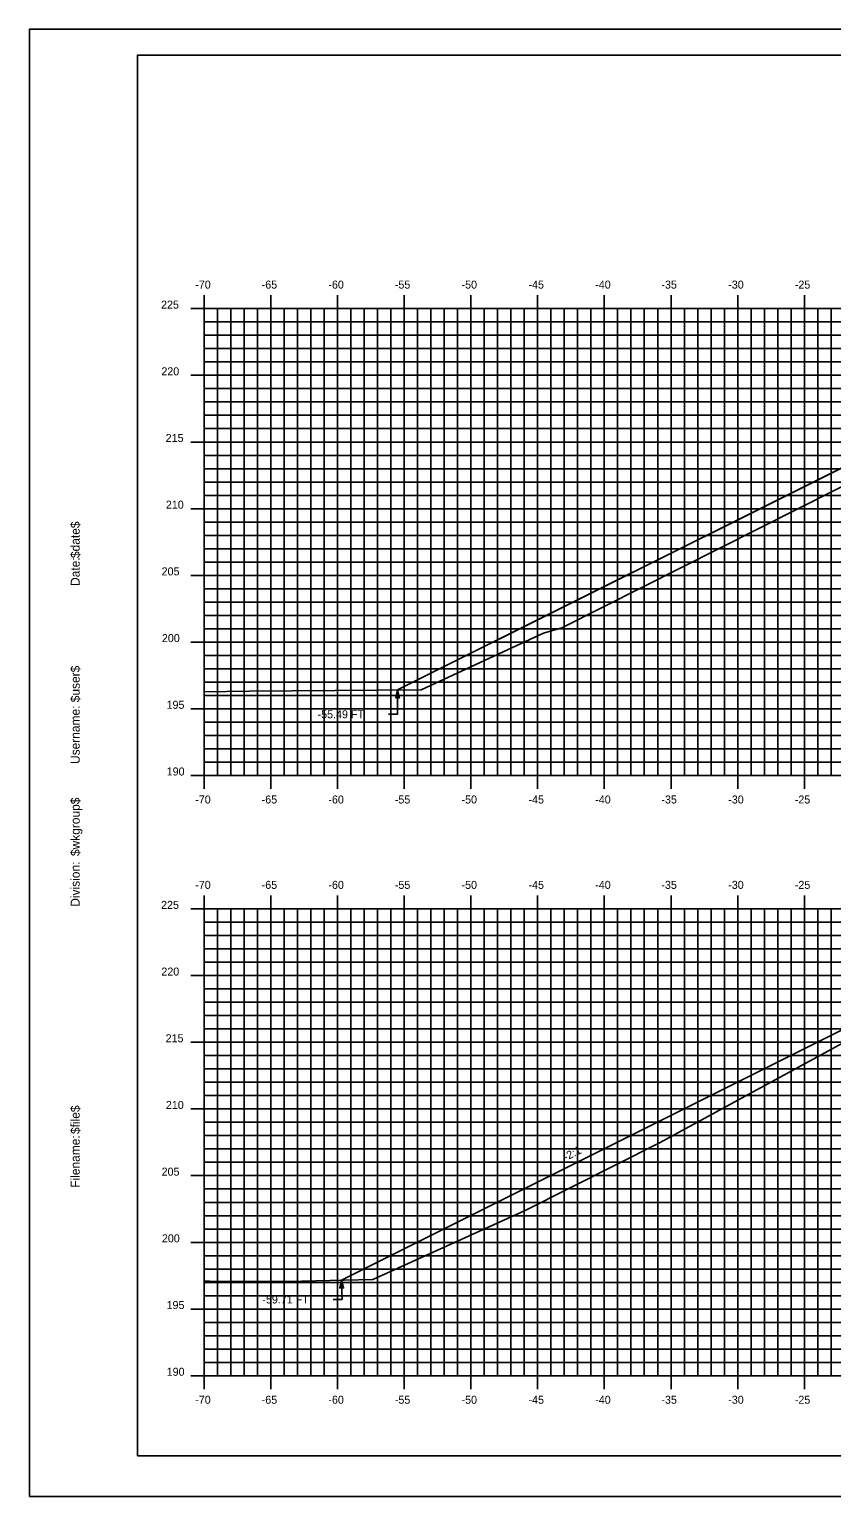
# Model space of a CAD drawing. Extents: x 1138320 to 1138490, y 608981 to 609091.
# Drawn here: x 1138319.6 to 1138379.7, y 608981.3 to 609091.3 of the extents above; entities that cross this region are included whole.
import ezdxf

# ---------------------------------------------------------------- set-up
doc = ezdxf.new("R2010")
doc.units = 0
for name, color, linetype in [('ANNOTATION', 7, 'Continuous'), ('BORDER', 7, 'Continuous'), ('D_Roadway_SlopeLines', 7, 'Continuous'), ('D_Roadway_SubGrade', 7, 'Continuous'), ('D_Text_Standard', 7, 'Continuous'), ('H_V ANNOTATION', 7, 'Continuous'), ('MAJOR', 7, 'Continuous'), ('MINOR', 7, 'Continuous'), ('PLOT BOUNDARY', 7, 'Continuous'), ('S_Roadway_Centerline', 7, 'Continuous')]:
    doc.layers.add(name, color=color, linetype=linetype)

msp = doc.modelspace()

# ---------------------------------------------------------------- linework, layer by layer
for points in [[(1138347.19, 609041.75), (1138377.76, 609057.04), (1138379.76, 609058.04), (1138384.68, 609060.5), (1138384.68, 609060.5), (1138391.68, 609060.78), (1138402.68, 609061), (1138413.68, 609060.78), (1138420.68, 609060.5), (1138425.6, 609058.04), (1138427.6, 609057.04), (1138456.11, 609042.78)], [(1138342.97, 608997.5), (1138378.75, 609015.39), (1138380.75, 609016.39), (1138385.71, 609018.87), (1138385.71, 609018.87), (1138391.68, 609019.11), (1138402.68, 609019.33), (1138413.68, 609019.11), (1138420.17, 609018.85), (1138425.1, 609016.38), (1138427.1, 609015.38), (1138461.72, 608998.08)]]:
    msp.add_lwpolyline(points)
at = {"layer": 'BORDER'}
msp.add_lwpolyline([(1138327.68, 608984.34), (1138487.68, 608984.34), (1138487.68, 609089.34), (1138327.68, 609089.34)], close=True, dxfattribs=at)
at = {"layer": 'D_Roadway_SlopeLines'}
for points in [[(1138379.76, 609058.04), (1138377.76, 609057.04)], [(1138377.76, 609057.04), (1138347.19, 609041.75)], [(1138380.75, 609016.39), (1138378.75, 609015.39)], [(1138378.75, 609015.39), (1138342.97, 608997.5)]]:
    msp.add_lwpolyline(points, dxfattribs=at)
at = {"layer": 'D_Roadway_SubGrade'}
msp.add_lwpolyline([(1138384.68, 609060.5), (1138382.68, 609059.5), (1138347.19, 609041.75)], dxfattribs=at)
at = {"layer": 'D_Text_Standard'}
for points in [[(1138347.19, 609041.75), (1138347.19, 609039.93), (1138346.51, 609039.93)], [(1138342.97, 608997.5), (1138343.03, 608996.06), (1138342.35, 608996.06)]]:
    msp.add_lwpolyline(points, dxfattribs=at)
for points in [[(1138347.19, 609041.75), (1138347.34, 609041.17), (1138347.05, 609041.17)], [(1138342.97, 608997.5), (1138343.14, 608996.93), (1138342.85, 608996.92)]]:
    msp.add_lwpolyline(points, close=True, dxfattribs=at)
at = {"layer": 'MAJOR'}
for p, q in [((1138332.68, 609071.34), (1138332.68, 609070.34)), ((1138337.68, 609071.34), (1138337.68, 609070.34)), ((1138342.68, 609071.34), (1138342.68, 609070.34)), ((1138347.68, 609071.34), (1138347.68, 609070.34)), ((1138352.68, 609071.34), (1138352.68, 609070.34)), ((1138357.68, 609071.34), (1138357.68, 609070.34)), ((1138362.68, 609071.34), (1138362.68, 609070.34)), ((1138367.68, 609071.34), (1138367.68, 609070.34)), ((1138372.68, 609071.34), (1138372.68, 609070.34)), ((1138377.68, 609071.34), (1138377.68, 609070.34)), ((1138331.68, 609070.34), (1138332.68, 609070.34)), ((1138332.68, 609070.34), (1138472.68, 609070.34)), ((1138332.68, 609035.34), (1138332.68, 609070.34)), ((1138332.68, 609035.34), (1138332.68, 609070.34)), ((1138332.68, 609070.34), (1138472.68, 609070.34)), ((1138337.68, 609035.34), (1138337.68, 609070.34)), ((1138342.68, 609035.34), (1138342.68, 609070.34)), ((1138347.68, 609035.34), (1138347.68, 609070.34)), ((1138352.68, 609035.34), (1138352.68, 609070.34)), ((1138357.68, 609035.34), (1138357.68, 609070.34)), ((1138362.68, 609035.34), (1138362.68, 609070.34)), ((1138367.68, 609035.34), (1138367.68, 609070.34)), ((1138372.68, 609035.34), (1138372.68, 609070.34)), ((1138377.68, 609035.34), (1138377.68, 609070.34)), ((1138331.68, 609065.34), (1138332.68, 609065.34)), ((1138332.68, 609065.34), (1138472.68, 609065.34)), ((1138331.68, 609060.34), (1138332.68, 609060.34)), ((1138332.68, 609060.34), (1138472.68, 609060.34)), ((1138331.68, 609055.34), (1138332.68, 609055.34)), ((1138332.68, 609055.34), (1138472.68, 609055.34)), ((1138331.68, 609050.34), (1138332.68, 609050.34)), ((1138332.68, 609050.34), (1138472.68, 609050.34)), ((1138331.68, 609045.34), (1138332.68, 609045.34)), ((1138332.68, 609045.34), (1138472.68, 609045.34)), ((1138331.68, 609040.34), (1138332.68, 609040.34)), ((1138332.68, 609040.34), (1138472.68, 609040.34)), ((1138331.68, 609035.34), (1138332.68, 609035.34)), ((1138332.68, 609035.34), (1138472.68, 609035.34)), ((1138332.68, 609035.34), (1138472.68, 609035.34)), ((1138332.68, 609034.33), (1138332.68, 609035.34)), ((1138337.68, 609034.33), (1138337.68, 609035.34)), ((1138342.68, 609034.33), (1138342.68, 609035.34)), ((1138347.68, 609034.33), (1138347.68, 609035.34)), ((1138352.68, 609034.33), (1138352.68, 609035.34)), ((1138357.68, 609034.33), (1138357.68, 609035.34)), ((1138362.68, 609034.33), (1138362.68, 609035.34)), ((1138367.68, 609034.33), (1138367.68, 609035.34)), ((1138372.68, 609034.33), (1138372.68, 609035.34)), ((1138377.68, 609034.33), (1138377.68, 609035.34)), ((1138332.68, 609026.34), (1138332.68, 609025.34)), ((1138337.68, 609026.34), (1138337.68, 609025.34)), ((1138342.68, 609026.34), (1138342.68, 609025.34)), ((1138347.68, 609026.34), (1138347.68, 609025.34)), ((1138352.68, 609026.34), (1138352.68, 609025.34)), ((1138357.68, 609026.34), (1138357.68, 609025.34)), ((1138362.68, 609026.34), (1138362.68, 609025.34)), ((1138367.68, 609026.34), (1138367.68, 609025.34)), ((1138372.68, 609026.34), (1138372.68, 609025.34)), ((1138377.68, 609026.34), (1138377.68, 609025.34)), ((1138331.68, 609025.34), (1138332.68, 609025.34)), ((1138332.68, 609025.34), (1138472.68, 609025.34)), ((1138332.68, 608990.34), (1138332.68, 609025.34)), ((1138332.68, 608990.34), (1138332.68, 609025.34)), ((1138332.68, 609025.34), (1138472.68, 609025.34)), ((1138337.68, 608990.34), (1138337.68, 609025.34)), ((1138342.68, 608990.34), (1138342.68, 609025.34)), ((1138347.68, 608990.34), (1138347.68, 609025.34)), ((1138352.68, 608990.34), (1138352.68, 609025.34)), ((1138357.68, 608990.34), (1138357.68, 609025.34)), ((1138362.68, 608990.34), (1138362.68, 609025.34)), ((1138367.68, 608990.34), (1138367.68, 609025.34)), ((1138372.68, 608990.34), (1138372.68, 609025.34)), ((1138377.68, 608990.34), (1138377.68, 609025.34)), ((1138331.68, 609020.34), (1138332.68, 609020.34)), ((1138332.68, 609020.34), (1138472.68, 609020.34)), ((1138331.68, 609015.34), (1138332.68, 609015.34)), ((1138332.68, 609015.34), (1138472.68, 609015.34)), ((1138331.68, 609010.34), (1138332.68, 609010.34)), ((1138332.68, 609010.34), (1138472.68, 609010.34)), ((1138331.68, 609005.34), (1138332.68, 609005.34)), ((1138332.68, 609005.34), (1138472.68, 609005.34)), ((1138331.68, 609000.34), (1138332.68, 609000.34)), ((1138332.68, 609000.34), (1138472.68, 609000.34)), ((1138331.68, 608995.34), (1138332.68, 608995.34)), ((1138332.68, 608995.34), (1138472.68, 608995.34)), ((1138331.68, 608990.34), (1138332.68, 608990.34)), ((1138332.68, 608990.34), (1138472.68, 608990.34)), ((1138332.68, 608990.34), (1138472.68, 608990.34)), ((1138332.68, 608989.33), (1138332.68, 608990.34)), ((1138337.68, 608989.33), (1138337.68, 608990.34)), ((1138342.68, 608989.33), (1138342.68, 608990.34)), ((1138347.68, 608989.33), (1138347.68, 608990.34)), ((1138352.68, 608989.33), (1138352.68, 608990.34)), ((1138357.68, 608989.33), (1138357.68, 608990.34)), ((1138362.68, 608989.33), (1138362.68, 608990.34)), ((1138367.68, 608989.33), (1138367.68, 608990.34)), ((1138372.68, 608989.33), (1138372.68, 608990.34)), ((1138377.68, 608989.33), (1138377.68, 608990.34))]:
    msp.add_line(p, q, dxfattribs=at)
at = {"layer": 'MINOR'}
for p, q in [((1138333.68, 609035.34), (1138333.68, 609070.34)), ((1138334.68, 609035.34), (1138334.68, 609070.34)), ((1138335.68, 609035.34), (1138335.68, 609070.34)), ((1138336.68, 609035.34), (1138336.68, 609070.34)), ((1138338.68, 609035.34), (1138338.68, 609070.34)), ((1138339.68, 609035.34), (1138339.68, 609070.34)), ((1138340.68, 609035.34), (1138340.68, 609070.34)), ((1138341.68, 609035.34), (1138341.68, 609070.34)), ((1138343.68, 609035.34), (1138343.68, 609070.34)), ((1138344.68, 609035.34), (1138344.68, 609070.34)), ((1138345.68, 609035.34), (1138345.68, 609070.34)), ((1138346.68, 609035.34), (1138346.68, 609070.34)), ((1138348.68, 609035.34), (1138348.68, 609070.34)), ((1138349.68, 609035.34), (1138349.68, 609070.34)), ((1138350.68, 609035.34), (1138350.68, 609070.34)), ((1138351.68, 609035.34), (1138351.68, 609070.34)), ((1138353.68, 609035.34), (1138353.68, 609070.34)), ((1138354.68, 609035.34), (1138354.68, 609070.34)), ((1138355.68, 609035.34), (1138355.68, 609070.34)), ((1138356.68, 609035.34), (1138356.68, 609070.34)), ((1138358.68, 609035.34), (1138358.68, 609070.34)), ((1138359.68, 609035.34), (1138359.68, 609070.34)), ((1138360.68, 609035.34), (1138360.68, 609070.34)), ((1138361.68, 609035.34), (1138361.68, 609070.34)), ((1138363.68, 609035.34), (1138363.68, 609070.34)), ((1138364.68, 609035.34), (1138364.68, 609070.34)), ((1138365.68, 609035.34), (1138365.68, 609070.34)), ((1138366.68, 609035.34), (1138366.68, 609070.34)), ((1138368.68, 609035.34), (1138368.68, 609070.34)), ((1138369.68, 609035.34), (1138369.68, 609070.34)), ((1138370.68, 609035.34), (1138370.68, 609070.34)), ((1138371.68, 609035.34), (1138371.68, 609070.34)), ((1138373.68, 609035.34), (1138373.68, 609070.34)), ((1138374.68, 609035.34), (1138374.68, 609070.34)), ((1138375.68, 609035.34), (1138375.68, 609070.34)), ((1138376.68, 609035.34), (1138376.68, 609070.34)), ((1138378.68, 609035.34), (1138378.68, 609070.34)), ((1138379.68, 609035.34), (1138379.68, 609070.34)), ((1138332.68, 609069.34), (1138472.68, 609069.34)), ((1138332.68, 609069.34), (1138333.68, 609069.34)), ((1138332.68, 609068.34), (1138472.68, 609068.34)), ((1138332.68, 609068.34), (1138333.68, 609068.34)), ((1138332.68, 609067.34), (1138472.68, 609067.34)), ((1138332.68, 609067.34), (1138333.68, 609067.34)), ((1138332.68, 609066.34), (1138472.68, 609066.34)), ((1138332.68, 609066.34), (1138333.68, 609066.34)), ((1138332.68, 609064.34), (1138472.68, 609064.34)), ((1138332.68, 609064.34), (1138333.68, 609064.34)), ((1138332.68, 609063.34), (1138472.68, 609063.34)), ((1138332.68, 609063.34), (1138333.68, 609063.34)), ((1138332.68, 609062.34), (1138472.68, 609062.34)), ((1138332.68, 609062.34), (1138333.68, 609062.34)), ((1138332.68, 609061.34), (1138472.68, 609061.34)), ((1138332.68, 609061.34), (1138333.68, 609061.34)), ((1138332.68, 609059.34), (1138472.68, 609059.34)), ((1138332.68, 609059.34), (1138333.68, 609059.34)), ((1138332.68, 609058.34), (1138472.68, 609058.34)), ((1138332.68, 609058.34), (1138333.68, 609058.34)), ((1138332.68, 609057.34), (1138472.68, 609057.34)), ((1138332.68, 609057.34), (1138333.68, 609057.34)), ((1138332.68, 609056.34), (1138472.68, 609056.34)), ((1138332.68, 609056.34), (1138333.68, 609056.34)), ((1138332.68, 609054.34), (1138472.68, 609054.34)), ((1138332.68, 609054.34), (1138333.68, 609054.34)), ((1138332.68, 609053.34), (1138472.68, 609053.34)), ((1138332.68, 609053.34), (1138333.68, 609053.34)), ((1138332.68, 609052.34), (1138472.68, 609052.34)), ((1138332.68, 609052.34), (1138333.68, 609052.34)), ((1138332.68, 609051.34), (1138472.68, 609051.34)), ((1138332.68, 609051.34), (1138333.68, 609051.34)), ((1138332.68, 609049.34), (1138472.68, 609049.34)), ((1138332.68, 609049.34), (1138333.68, 609049.34)), ((1138332.68, 609048.34), (1138472.68, 609048.34)), ((1138332.68, 609048.34), (1138333.68, 609048.34)), ((1138332.68, 609047.34), (1138472.68, 609047.34)), ((1138332.68, 609047.34), (1138333.68, 609047.34)), ((1138332.68, 609046.34), (1138472.68, 609046.34)), ((1138332.68, 609046.34), (1138333.68, 609046.34)), ((1138332.68, 609044.34), (1138472.68, 609044.34)), ((1138332.68, 609044.34), (1138333.68, 609044.34)), ((1138332.68, 609043.34), (1138472.68, 609043.34)), ((1138332.68, 609043.34), (1138333.68, 609043.34)), ((1138332.68, 609042.34), (1138472.68, 609042.34)), ((1138332.68, 609042.34), (1138333.68, 609042.34)), ((1138332.68, 609041.34), (1138472.68, 609041.34)), ((1138332.68, 609041.34), (1138333.68, 609041.34)), ((1138332.68, 609039.34), (1138472.68, 609039.34)), ((1138332.68, 609039.34), (1138333.68, 609039.34)), ((1138332.68, 609038.34), (1138472.68, 609038.34)), ((1138332.68, 609038.34), (1138333.68, 609038.34)), ((1138332.68, 609037.34), (1138472.68, 609037.34)), ((1138332.68, 609037.34), (1138333.68, 609037.34)), ((1138332.68, 609036.34), (1138472.68, 609036.34)), ((1138332.68, 609036.34), (1138333.68, 609036.34)), ((1138333.68, 608990.34), (1138333.68, 609025.34)), ((1138334.68, 608990.34), (1138334.68, 609025.34)), ((1138335.68, 608990.34), (1138335.68, 609025.34)), ((1138336.68, 608990.34), (1138336.68, 609025.34)), ((1138338.68, 608990.34), (1138338.68, 609025.34)), ((1138339.68, 608990.34), (1138339.68, 609025.34)), ((1138340.68, 608990.34), (1138340.68, 609025.34)), ((1138341.68, 608990.34), (1138341.68, 609025.34)), ((1138343.68, 608990.34), (1138343.68, 609025.34)), ((1138344.68, 608990.34), (1138344.68, 609025.34)), ((1138345.68, 608990.34), (1138345.68, 609025.34)), ((1138346.68, 608990.34), (1138346.68, 609025.34)), ((1138348.68, 608990.34), (1138348.68, 609025.34)), ((1138349.68, 608990.34), (1138349.68, 609025.34)), ((1138350.68, 608990.34), (1138350.68, 609025.34)), ((1138351.68, 608990.34), (1138351.68, 609025.34)), ((1138353.68, 608990.34), (1138353.68, 609025.34)), ((1138354.68, 608990.34), (1138354.68, 609025.34)), ((1138355.68, 608990.34), (1138355.68, 609025.34)), ((1138356.68, 608990.34), (1138356.68, 609025.34)), ((1138358.68, 608990.34), (1138358.68, 609025.34)), ((1138359.68, 608990.34), (1138359.68, 609025.34)), ((1138360.68, 608990.34), (1138360.68, 609025.34)), ((1138361.68, 608990.34), (1138361.68, 609025.34)), ((1138363.68, 608990.34), (1138363.68, 609025.34)), ((1138364.68, 608990.34), (1138364.68, 609025.34)), ((1138365.68, 608990.34), (1138365.68, 609025.34)), ((1138366.68, 608990.34), (1138366.68, 609025.34)), ((1138368.68, 608990.34), (1138368.68, 609025.34)), ((1138369.68, 608990.34), (1138369.68, 609025.34)), ((1138370.68, 608990.34), (1138370.68, 609025.34)), ((1138371.68, 608990.34), (1138371.68, 609025.34)), ((1138373.68, 608990.34), (1138373.68, 609025.34)), ((1138374.68, 608990.34), (1138374.68, 609025.34)), ((1138375.68, 608990.34), (1138375.68, 609025.34)), ((1138376.68, 608990.34), (1138376.68, 609025.34)), ((1138378.68, 608990.34), (1138378.68, 609025.34)), ((1138379.68, 608990.34), (1138379.68, 609025.34)), ((1138332.68, 609024.34), (1138472.68, 609024.34)), ((1138332.68, 609024.34), (1138333.68, 609024.34)), ((1138332.68, 609023.34), (1138472.68, 609023.34)), ((1138332.68, 609023.34), (1138333.68, 609023.34)), ((1138332.68, 609022.34), (1138472.68, 609022.34)), ((1138332.68, 609022.34), (1138333.68, 609022.34)), ((1138332.68, 609021.34), (1138472.68, 609021.34)), ((1138332.68, 609021.34), (1138333.68, 609021.34)), ((1138332.68, 609019.34), (1138472.68, 609019.34)), ((1138332.68, 609019.34), (1138333.68, 609019.34)), ((1138332.68, 609018.34), (1138472.68, 609018.34)), ((1138332.68, 609018.34), (1138333.68, 609018.34)), ((1138332.68, 609017.34), (1138472.68, 609017.34)), ((1138332.68, 609017.34), (1138333.68, 609017.34)), ((1138332.68, 609016.34), (1138472.68, 609016.34)), ((1138332.68, 609016.34), (1138333.68, 609016.34)), ((1138332.68, 609014.34), (1138472.68, 609014.34)), ((1138332.68, 609014.34), (1138333.68, 609014.34)), ((1138332.68, 609013.34), (1138472.68, 609013.34)), ((1138332.68, 609013.34), (1138333.68, 609013.34)), ((1138332.68, 609012.34), (1138472.68, 609012.34)), ((1138332.68, 609012.34), (1138333.68, 609012.34)), ((1138332.68, 609011.34), (1138472.68, 609011.34)), ((1138332.68, 609011.34), (1138333.68, 609011.34)), ((1138332.68, 609009.34), (1138472.68, 609009.34)), ((1138332.68, 609009.34), (1138333.68, 609009.34)), ((1138332.68, 609008.34), (1138472.68, 609008.34)), ((1138332.68, 609008.34), (1138333.68, 609008.34)), ((1138332.68, 609007.34), (1138472.68, 609007.34)), ((1138332.68, 609007.34), (1138333.68, 609007.34)), ((1138332.68, 609006.34), (1138472.68, 609006.34)), ((1138332.68, 609006.34), (1138333.68, 609006.34)), ((1138332.68, 609004.34), (1138472.68, 609004.34)), ((1138332.68, 609004.34), (1138333.68, 609004.34)), ((1138332.68, 609003.34), (1138472.68, 609003.34)), ((1138332.68, 609003.34), (1138333.68, 609003.34)), ((1138332.68, 609002.34), (1138472.68, 609002.34)), ((1138332.68, 609002.34), (1138333.68, 609002.34)), ((1138332.68, 609001.34), (1138472.68, 609001.34)), ((1138332.68, 609001.34), (1138333.68, 609001.34)), ((1138332.68, 608999.34), (1138472.68, 608999.34)), ((1138332.68, 608999.34), (1138333.68, 608999.34)), ((1138332.68, 608998.34), (1138472.68, 608998.34)), ((1138332.68, 608998.34), (1138333.68, 608998.34)), ((1138332.68, 608997.34), (1138472.68, 608997.34)), ((1138332.68, 608997.34), (1138333.68, 608997.34)), ((1138332.68, 608996.34), (1138472.68, 608996.34)), ((1138332.68, 608996.34), (1138333.68, 608996.34)), ((1138332.68, 608994.34), (1138472.68, 608994.34)), ((1138332.68, 608994.34), (1138333.68, 608994.34)), ((1138332.68, 608993.34), (1138472.68, 608993.34)), ((1138332.68, 608993.34), (1138333.68, 608993.34)), ((1138332.68, 608992.34), (1138472.68, 608992.34)), ((1138332.68, 608992.34), (1138333.68, 608992.34)), ((1138332.68, 608991.34), (1138472.68, 608991.34)), ((1138332.68, 608991.34), (1138333.68, 608991.34))]:
    msp.add_line(p, q, dxfattribs=at)
at = {"layer": 'PLOT BOUNDARY'}
msp.add_lwpolyline([(1138319.59, 608981.28), (1138489.59, 608981.28), (1138489.59, 609091.28), (1138319.59, 609091.28)], close=True, dxfattribs=at)
at = {"layer": 'S_Roadway_Centerline'}
for points in [[(1138332.68, 609041.62), (1138336.05, 609041.67), (1138348.96, 609041.77), (1138358.12, 609046), (1138359.49, 609046.42), (1138362.57, 609047.96), (1138383.07, 609058.3), (1138388, 609060.84), (1138390.65, 609061.4), (1138391.41, 609061.55), (1138391.79, 609061.62), (1138402.25, 609061.76), (1138402.8, 609061.77), (1138412.48, 609061.63), (1138413.11, 609061.62), (1138413.26, 609061.6), (1138416.45, 609061.5), (1138419.52, 609059.92), (1138450.84, 609043.12), (1138450.9, 609043.11), (1138451.52, 609042.96), (1138472.68, 609042.15)], [(1138332.68, 608997.42), (1138333.11, 608997.42), (1138338.92, 608997.4), (1138345.34, 608997.56), (1138356.74, 609002.74), (1138366.82, 609007.79), (1138384.8, 609017.59)]]:
    msp.add_lwpolyline(points, dxfattribs=at)

# ---------------------------------------------------------------- texts
at = {"layer": 'ANNOTATION'}
msp.add_text('-2:1', height=0.6, rotation=26.5651, dxfattribs=at).set_placement((1138359.79, 609006.43))
at = {"layer": 'BORDER'}
for s, p in [('$date$', (1138323.36, 609051.64)), ('Date:', (1138323.36, 609049.55)), ('$user$', (1138323.36, 609040.83)), ('Username:', (1138323.36, 609036.2)), ('$wkgroup$', (1138323.36, 609029.3)), ('Division:', (1138323.36, 609025.5)), ('$file$', (1138323.36, 609008.46)), ('Filename:', (1138323.36, 609004.43))]:
    msp.add_text(s, height=0.67, rotation=90, dxfattribs=at).set_placement(p)
at = {"layer": 'D_Text_Standard'}
for s, p in [('-55.49 FT', (1138341.19, 609039.63)), ('-59.71 FT', (1138337.05, 608995.76))]:
    msp.add_text(s, height=0.6, dxfattribs=at).set_placement(p)
at = {"layer": 'H_V ANNOTATION'}
for s, p in [('-70', (1138332.02, 609071.84)), ('-65', (1138337, 609071.84)), ('-60', (1138342, 609071.84)), ('-55', (1138346.98, 609071.84)), ('-50', (1138351.98, 609071.84)), ('-45', (1138357, 609071.84)), ('-40', (1138362, 609071.84)), ('-35', (1138366.96, 609071.84)), ('-30', (1138371.97, 609071.84)), ('-25', (1138376.96, 609071.84)), ('225', (1138329.46, 609070.34)), ('220', (1138329.48, 609065.34)), ('215', (1138329.8, 609060.34)), ('210', (1138329.82, 609055.34)), ('205', (1138329.5, 609050.34)), ('200', (1138329.52, 609045.34)), ('195', (1138329.87, 609040.34)), ('190', (1138329.88, 609035.34)), ('-70', (1138332.02, 609033.24)), ('-65', (1138337, 609033.24)), ('-60', (1138342, 609033.24)), ('-55', (1138346.98, 609033.24)), ('-50', (1138351.98, 609033.24)), ('-45', (1138357, 609033.24)), ('-40', (1138362, 609033.24)), ('-35', (1138366.96, 609033.24)), ('-30', (1138371.97, 609033.24)), ('-25', (1138376.96, 609033.24)), ('-70', (1138332.02, 609026.84)), ('-65', (1138337, 609026.84)), ('-60', (1138342, 609026.84)), ('-55', (1138346.98, 609026.84)), ('-50', (1138351.98, 609026.84)), ('-45', (1138357, 609026.84)), ('-40', (1138362, 609026.84)), ('-35', (1138366.96, 609026.84)), ('-30', (1138371.97, 609026.84)), ('-25', (1138376.96, 609026.84)), ('225', (1138329.46, 609025.34)), ('220', (1138329.48, 609020.34)), ('215', (1138329.8, 609015.34)), ('210', (1138329.82, 609010.34)), ('205', (1138329.5, 609005.34)), ('200', (1138329.52, 609000.34)), ('195', (1138329.87, 608995.34)), ('190', (1138329.88, 608990.34)), ('-70', (1138332.02, 608988.24)), ('-65', (1138337, 608988.24)), ('-60', (1138342, 608988.24)), ('-55', (1138346.98, 608988.24)), ('-50', (1138351.98, 608988.24)), ('-45', (1138357, 608988.24)), ('-40', (1138362, 608988.24)), ('-35', (1138366.96, 608988.24)), ('-30', (1138371.97, 608988.24)), ('-25', (1138376.96, 608988.24))]:
    msp.add_text(s, height=0.6, dxfattribs=at).set_placement(p)
at = {"layer": 'MAJOR'}
for p in [(1138332.67, 609035.34), (1138332.67, 608990.34)]:
    msp.add_text('-', height=0.006, dxfattribs=at).set_placement(p)

doc.saveas('drawing.dxf')
